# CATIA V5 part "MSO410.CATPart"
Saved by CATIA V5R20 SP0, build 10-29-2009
Part number: MSO410
Definition: NONE
Nomenclature: MSO410
Source: Unknown
Description: MSO410
Bounding box of the stored display mesh (mm): x 0 to 12, y -5 to 5, z -5 to 5
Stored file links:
  C:\Users\Utente\Desktop\IO LAVORO\3D X SITO CF\X SITO\PLASTICA\CFMR\MSO410.CATPart
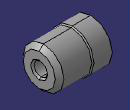
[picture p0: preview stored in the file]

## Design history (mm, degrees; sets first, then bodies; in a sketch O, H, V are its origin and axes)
Body1 "MSO410" (main body)
  Solid1: solid without history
